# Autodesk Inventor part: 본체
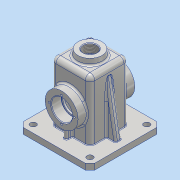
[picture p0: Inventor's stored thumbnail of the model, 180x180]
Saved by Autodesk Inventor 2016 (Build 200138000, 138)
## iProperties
Created: 2018-10
Part Number: 본체
Material: 알루미늄 6061
Document SubType Name: Modeling
Designer: user
Density: 2.7 g/cm^3
Appearance: 알루미늄 - 평지
Mass: 793.708 g
Surface Area: 900.844 cm^2
Volume: 293.966 cm^3
Author: user
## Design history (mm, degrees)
sketch "스케치1"
  geometry: L1 (-60, -60)-(60, -60); L2 (60, -60)-(60, 60); L3 (60, 60)-(-60, 60); L4 (-60, 60)-(-60, -60); L5 (-60, -60)-(60, 60); L6 (60, -60)-(-60, 60); 1 further point
  constraints: 12 end point, 2 midpoint, 2 parallel, 1 horizontal, 1 perpendicular
  dimensions: "d0" = 120 distance of L3.end L2.end; "d1" = 120 distance of L2.end L1.end
extrude "돌출1" new body sketch "스케치1" distance "d2" = 10; taper "d3" = 0 deg
sketch "스케치2"
  geometry: L1 (-32.5, 32.5)-(32.5, 32.5); L2 (32.5, 32.5)-(32.5, -32.5); L3 (32.5, -32.5)-(-32.5, -32.5); L4 (-32.5, -32.5)-(-32.5, 32.5); L5 (-32.5, 32.5)-(32.5, -32.5); L6 (32.5, 32.5)-(-32.5, -32.5); 1 further point
  constraints: 12 end point, 2 midpoint, 2 parallel, 1 horizontal, 1 perpendicular
  dimensions: "d4" = 65 distance of L2.end L3.end; "d5" = 65 distance of L1.end L2.end
extrude "돌출2" join sketch "스케치2" distance "d6" = 100; taper "d7" = 0 deg
node "작업 평면1"
sketch "스케치4"
  geometry: L1 (47.5, 47.5)-(-47.5, 47.5); L2 (-47.5, 47.5)-(-47.5, -47.5); L3 (-47.5, -47.5)-(47.5, -47.5); L4 (47.5, -47.5)-(47.5, 47.5); L5 (47.5, 47.5)-(-47.5, -47.5); L6 (-47.5, 47.5)-(47.5, -47.5); 5 further points
  constraints: 12 end point, 4 coincident, 2 midpoint, 2 parallel, 1 horizontal, 1 perpendicular
  dimensions: "d12" = 95 distance of L3.end L2.end; "d13" = 95 distance of L2.end L1.end
hole "구멍1" sketch "스케치4" at (47.5, -47.5), (47.5, 47.5), (-47.5, 47.5), (-47.5, -47.5) diameter "d14" = 10; stored, may be unused: countersink angle "d18" = 90 deg, drill point angle "d20" = 118 deg; dims "d15" = 6, "d16" = 4, "d17" = 2, "d19" = 8
feature "쉘1" dims "d21" = 10, "d22" = 5
sketch "스케치5"
  geometry: L1 (5, -10)-(60, -10) reference; C1 r 27.5 at (32.5, 45); 2 further points
  constraints: 1 centre point, 1 midpoint, 1 vertical alignment
  dimensions: "d23" = 55 diameter of C1; "d24" = 55 distance from line of L1 C1.centre
extrude "돌출4" join sketch "스케치5" distance "d25" = 15; taper "d26" = 0 deg
sketch "스케치6"
  geometry: L1 (65, 0)-(0, 0) reference; L2 (29.5, 0)-(35.5, 0); L3 (35.5, 0)-(35.5, 23.956); L4 (35.5, 23.956)-(29.5, 23.956); L5 (29.5, 23.956)-(29.5, 0); 2 further points
  constraints: 8 end point, 2 parallel, 1 horizontal, 1 midpoint, 1 perpendicular, 1 point on line, 1 vertical alignment
  dimensions: "d27" = 6 distance of L4.end L3.end; "d28" = 23.95607 distance of L2.end L3.end
extrude "돌출5" join sketch "스케치6" distance "d29" = 10; taper "d30" = 0 deg
sketch "스케치7"
  geometry: C1 r 27.5 at (0, 0) reference; 2 further points
  constraints: 1 vertical alignment
  dimensions: "d31" = 21 distance of C1.centre point (0, 21)
hole "구멍2" sketch "스케치7" at (0, 21) diameter "d32" = 3.242; stored, may be unused: countersink angle "d36" = 90 deg, drill point angle "d38" = 118 deg; dims "d33" = 8, "d34" = 4, "d35" = 2, "d37" = 10
node "작업 평면2"
sketch "스케치9"
  geometry: C1 r 20 at (0, 0); 1 further point
  constraints: 1 centre point, 1 coincident
  dimensions: "d43" = 20 radius of C1
extrude "돌출6" join sketch "스케치9" distance "d44" = 10; taper "d45" = 7 deg
sketch "스케치10"
  geometry: L1 (-47.5, 82.5)-(-47.5, 27.5) reference; L2 (47.5, 82.5)-(47.5, 27.5) reference; L3 (-47.5, 55)-(47.5, 55); L4 (-47.5, 72.5)-(-30.5, 72.5); L5 (-30.5, 72.5)-(-30.5, 70); L6 (-30.5, 70)-(30.5, 70); L7 (30.5, 70)-(30.5, 72.5); L8 (30.5, 72.5)-(47.5, 72.5); 1 further point
  constraints: 12 end point, 4 point on line, 3 perpendicular, 2 midpoint, 1 collinear, 1 horizontal
  dimensions: "d46" = 17 distance of L4.start L4.end; "d47" = 35 diameter of L4 L3; "d48" = 30 diameter of L6 L3
revolve "회전1" sketch "스케치10" stored, may be unused: angle "d49" = 90 deg
sketch "스케치11"
  geometry: C1 r 20 at (0, 0) reference; 1 further point
  constraints: 1 coincident
hole "구멍3" sketch "스케치11" at (0, 0) diameter "d50" = 22.835; stored, may be unused: countersink angle "d54" = 90 deg, drill point angle "d56" = 118 deg; dims "d51" = 50, "d52" = 4, "d53" = 2, "d55" = 59.3
sketch "스케치12"
  geometry: L1 (32.5, 10)-(32.5, 110) reference; L2 (-60, 10)-(60, 10) reference; L3 (-32.5, 10)-(-32.5, 110) reference; L4 (32.5, 97.905)-(48, 10); L5 (-32.5, 97.905)-(-48, 10); L6 (60, 0)-(60, 10) reference; L7 (-60, 0)-(-60, 10) reference; 1 further point
  constraints: 4 end point, 4 point on line, 1 equal length
  dimensions: "d57" = 12 distance from line of L6 L4.end; "d58" = 10 deg angle of L6 L4; "d59" = 10 deg angle of L7 L5
extrude "돌출7" join sketch "스케치12" stored distance "d60" = 10; taper "d61" = 0 deg
chamfer "모따기1" distance "d62" = 1; stored, may be unused: second distance "d63" = 2, angle "d64" = 45 deg
chamfer "모따기2" distance "d65" = 8; stored, may be unused: second distance "d66" = 2, angle "d67" = 45 deg
fillet "모깎기1" dims "d68" = 8
fillet "모깎기2" dims "d69" = 8
fillet "모깎기3" dims "d70" = 3
fillet "모깎기4" dims "d71" = 3
fillet "모깎기5" dims "d72" = 3
fillet "모깎기6" dims "d73" = 0.3
fillet "모깎기7" dims "d74" = 1
sketch "스케치14"
  geometry: L1 (57, 0)-(57, 91) reference; L2 (44.5, -18)-(4.5, -18) reference; 2 further points
  constraints: 1 other
  dimensions: "d75" = 32.5 distance from line of L1 point (24.5, 8); "d76" = 26 distance from line of point (24.5, 8) L2
feature "엠보싱1" sketch "스케치14" dims "d0" = 120, "d1" = 120, "d12" = 95, "d13" = 95, "d77" = 0.5, "d78" = 0
fillet "모깎기8" dims "d79" = 3
node "솔리드1"
pattern_circular "원형 패턴1" dims angle "d40" = 360 deg
mirror "대칭1"
